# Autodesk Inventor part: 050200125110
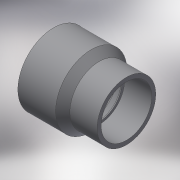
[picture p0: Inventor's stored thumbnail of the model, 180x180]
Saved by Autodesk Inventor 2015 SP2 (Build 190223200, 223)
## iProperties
Created: 2017-10
Part Number: 050200125110
Material: Generic
Description: PLASSON REDUCING SOCKET M.F.125(110)110 CEMENTED
Document SubType Name: Modeling
Designer: KIM
Density: 1 g/cm^3
Appearance: Default
Author: KIM
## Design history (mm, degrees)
derived "050200.ipt"
feature "Solid1::050200.ipt"
tag "TaggingFeature1"
body "Solid1"
other parameters: "d0" = 127, "d1" = 69, "d2" = 57, "d3" = 61, "d5" = 123, "d7" = 125, "d8" = 99, "d9" = 45 deg, "d12" = 1.1, "L_" = 69, "l_" = 61, "l_1" = 57, "E_" = 123, "H_" = 127, "D_" = 125, "d11" = 45 deg
